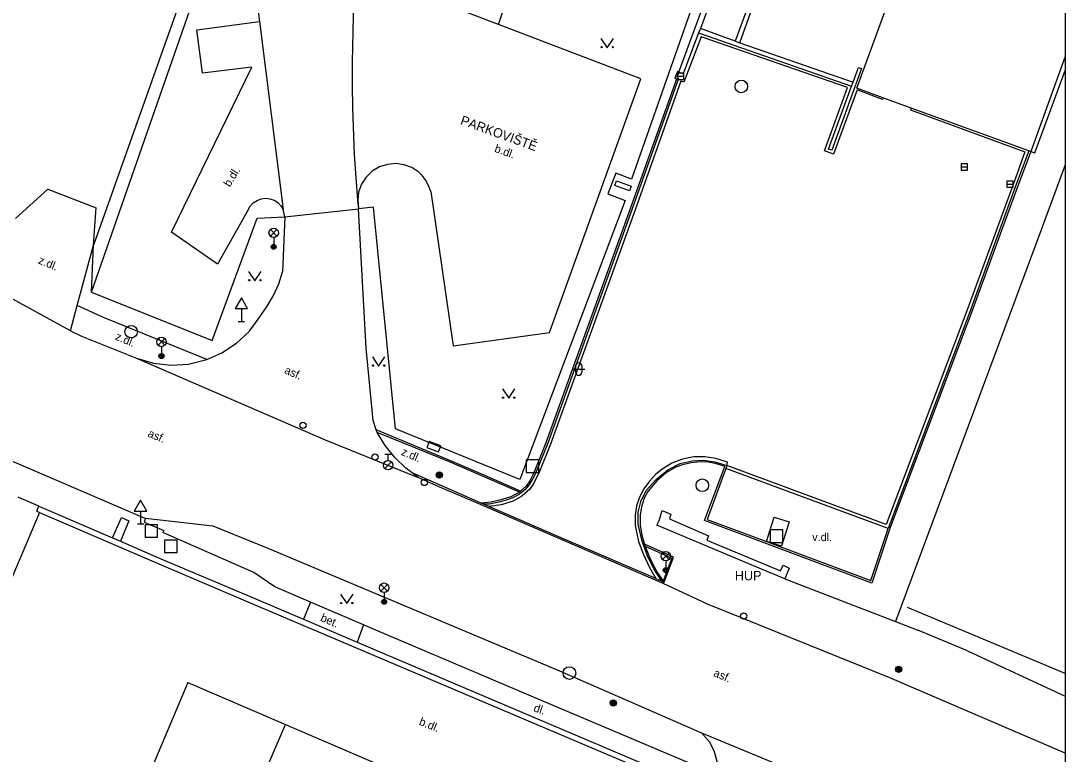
# Model space of a CAD drawing. Extents: x -596024 to -594475, y -1163820 to -1161957.
# Drawn here: x -594558.9 to -594475.5, y -1162309.5 to -1162250.9 of the extents above; entities that cross this region are included whole.
import ezdxf

# ---------------------------------------------------------------- set-up
doc = ezdxf.new("R2010")
doc.units = 0
for name, color, linetype in [('Level 10', 7, 'Continuous'), ('Level 11', 7, 'Continuous'), ('Level 14', 7, 'Continuous'), ('Level 24', 7, 'Continuous'), ('Level 25', 7, 'Continuous'), ('Level 26', 7, 'Continuous'), ('Level 27', 7, 'Continuous'), ('Level 28', 7, 'Continuous'), ('Level 33', 7, 'Continuous'), ('Level 34', 7, 'Continuous'), ('Level 36', 7, 'Continuous'), ('Level 40', 7, 'Continuous'), ('Level 41', 7, 'Continuous'), ('Level 5', 7, 'Continuous'), ('Level 7', 7, 'Continuous'), ('Level 8', 7, 'Continuous'), ('Vrstva 63', 7, 'Continuous')]:
    doc.layers.add(name, color=color, linetype=linetype)

msp = doc.modelspace()

# ---------------------------------------------------------------- linework, layer by layer
at = {"layer": 'Level 10'}
for points in [[(-594528.48, -1162197.8), (-594531.53, -1162207.45), (-594543.75, -1162242.57), (-594553.08, -1162268.85)], [(-594538.62, -1162240.19), (-594538.98, -1162241.19), (-594539.47, -1162242.7), (-594539.76, -1162243.72), (-594540.15, -1162245.26), (-594540.18, -1162246.41), (-594540.13, -1162248.13), (-594540.04, -1162249.27), (-594539.9, -1162250.41), (-594539.81, -1162250.98)], [(-594520.73, -1162251.23), (-594525.28, -1162249.49)], [(-594540.72, -1162266.03), (-594543.18, -1162270.36), (-594546.83, -1162267.81), (-594540.43, -1162254.62), (-594544.36, -1162255.11), (-594544.83, -1162251.66), (-594539.81, -1162250.98)], [(-594509.36, -1162255.56), (-594520.73, -1162251.23)], [(-594526.14, -1162264.55), (-594524.35, -1162276.86), (-594516.64, -1162275.82), (-594509.36, -1162255.56)], [(-594526.14, -1162264.55), (-594526.25, -1162264.2), (-594526.49, -1162263.71), (-594526.82, -1162263.27), (-594527.08, -1162263.02), (-594527.64, -1162262.65), (-594528.27, -1162262.42), (-594528.93, -1162262.33), (-594529.6, -1162262.39), (-594530.24, -1162262.6), (-594530.81, -1162262.94), (-594531.3, -1162263.41), (-594531.67, -1162263.97), (-594531.9, -1162264.6), (-594531.96, -1162265.22), (-594531.91, -1162265.94)], [(-594540.72, -1162266.03), (-594540.55, -1162265.72), (-594540.31, -1162265.46), (-594540.01, -1162265.27), (-594539.68, -1162265.14), (-594539.33, -1162265.1), (-594538.98, -1162265.13), (-594538.65, -1162265.25), (-594538.35, -1162265.44), (-594538.1, -1162265.69), (-594537.92, -1162265.99)], [(-594537.78, -1162266.59), (-594537.92, -1162265.99)], [(-594530.49, -1162283.58), (-594530.74, -1162282.84), (-594531.28, -1162277.05), (-594531.91, -1162265.94)], [(-594537.78, -1162266.59), (-594537.97, -1162270.97)], [(-594544.03, -1162277.97), (-594542.82, -1162277.43), (-594541.64, -1162276.66), (-594540.62, -1162275.69), (-594539.78, -1162274.56), (-594539.19, -1162273.72), (-594538.69, -1162272.86), (-594538.28, -1162271.93), (-594537.97, -1162270.97)], [(-594554.91, -1162275.67), (-594560.65, -1162272.54)], [(-594554.91, -1162275.67), (-594554.02, -1162276.1), (-594549.63, -1162277.87)], [(-594549.63, -1162277.87), (-594548.28, -1162278.26), (-594546.88, -1162278.42), (-594545.48, -1162278.33), (-594544.03, -1162277.97)], [(-594568.02, -1162282.24), (-594566.32, -1162283.19), (-594548.96, -1162290.64), (-594548.93, -1162290.64)], [(-594530.42, -1162283.78), (-594530.49, -1162283.58)], [(-594527.62, -1162287.02), (-594528.13, -1162286.64), (-594529.01, -1162285.78), (-594529.78, -1162284.83), (-594530.42, -1162283.78)], [(-594527.15, -1162287.38), (-594527.62, -1162287.02)], [(-594524.98, -1162288.34), (-594527.15, -1162287.38)], [(-594507.57, -1162295.84), (-594522.72, -1162289.3), (-594524.98, -1162288.34)], [(-594548.93, -1162290.64), (-594543.53, -1162291.24), (-594539.14, -1162293.01), (-594515.84, -1162302.8), (-594504.51, -1162307.75)], [(-594475.47, -1162309.374), (-594489.48, -1162303.37), (-594504.04, -1162297.48), (-594507.57, -1162295.84)], [(-594504.51, -1162307.75), (-594495.18, -1162311.63)]]:
    msp.add_lwpolyline(points, dxfattribs=at)
at = {"layer": 'Level 11'}
for points in [[(-594506.31, -1162255.02), (-594497.74, -1162231.74), (-594492.08, -1162216.4)], [(-594491.81, -1162216.78), (-594497.37, -1162231.89), (-594504.6, -1162251.54)], [(-594489.03, -1162217.83), (-594491.43, -1162224.29), (-594501.82, -1162252.55)], [(-594532.13, -1162246.88), (-594532.24, -1162248.72), (-594532.33, -1162250.55), (-594532.42, -1162254.23), (-594532.42, -1162256.07), (-594532.39, -1162257.91), (-594532.25, -1162261.59), (-594532.13, -1162263.43), (-594531.99, -1162265.26), (-594531.91, -1162265.94)], [(-594520.73, -1162251.23), (-594519.27, -1162246.86)], [(-594501.45, -1162252.68), (-594499.78, -1162247.95)], [(-594539.81, -1162250.98), (-594537.92, -1162265.99)], [(-594504.74, -1162251.9), (-594505.98, -1162255.17), (-594506.31, -1162255.02)], [(-594504.6, -1162251.54), (-594504.74, -1162251.9)], [(-594490.02, -1162257.08), (-594490.06, -1162257.2), (-594492.07, -1162256.45), (-594493.96, -1162261.58), (-594494.68, -1162261.31), (-594492.86, -1162256.26), (-594504.55, -1162252.2), (-594505.93, -1162255.83), (-594506.15, -1162255.76), (-594509.81, -1162266.01), (-594516.57, -1162284.73), (-594517.44, -1162286.89), (-594517.89, -1162287.83), (-594518.22, -1162288.3), (-594518.85, -1162288.88), (-594519.56, -1162289.26), (-594520.51, -1162289.56), (-594521.49, -1162289.7)], [(-594501.82, -1162252.55), (-594501.45, -1162252.68)], [(-594506.31, -1162255.02), (-594506.48, -1162255.43), (-594506.35, -1162255.53), (-594510.06, -1162265.93), (-594516.79, -1162284.63), (-594517.66, -1162286.8), (-594517.89, -1162287.33), (-594518.29, -1162287.99), (-594518.62, -1162288.36), (-594519.06, -1162288.72), (-594519.57, -1162289), (-594520.18, -1162289.23), (-594520.71, -1162289.36), (-594521.44, -1162289.5), (-594521.92, -1162289.51)], [(-594506.31, -1162255.02), (-594506.44, -1162254.97), (-594506.65, -1162255.48), (-594506.52, -1162255.58), (-594510.19, -1162265.87), (-594516.95, -1162284.61)], [(-594492.4, -1162255.82), (-594491.98, -1162254.66), (-594491.73, -1162254.75), (-594494.11, -1162261.26), (-594494.36, -1162261.17), (-594492.52, -1162256.14)], [(-594478.22, -1162261.36), (-594477.89, -1162261.48), (-594475.47, -1162254.887)], [(-594492.52, -1162256.14), (-594492.4, -1162255.82)], [(-594487.76, -1162257.9), (-594487.81, -1162258.05), (-594478.68, -1162261.39), (-594479.42, -1162263.5), (-594483.31, -1162274.08), (-594489.76, -1162291.13), (-594502.49, -1162286.43)], [(-594478.22, -1162261.36), (-594479.28, -1162264.19), (-594482.94, -1162274.22), (-594489.43, -1162291.38), (-594490.91, -1162295.81), (-594504.26, -1162290.81), (-594502.65, -1162286.5), (-594503.31, -1162286.28), (-594503.96, -1162286.16), (-594504.63, -1162286.13), (-594505.34, -1162286.2), (-594506.03, -1162286.36), (-594506.55, -1162286.56), (-594507.31, -1162286.98), (-594508.09, -1162287.65), (-594508.8, -1162288.5), (-594509.08, -1162289.04), (-594509.31, -1162289.71), (-594509.42, -1162290.38), (-594509.41, -1162291.2), (-594509.25, -1162292.08), (-594509.07, -1162292.71)], [(-594478.36, -1162261.31), (-594479.42, -1162264.14), (-594483.08, -1162274.17), (-594489.61, -1162291.44)], [(-594475.47, -1162262.421), (-594477.84, -1162268.85), (-594489.03, -1162298.88)], [(-594511.3, -1162263.71), (-594510.13, -1162264.14), (-594510.26, -1162264.51), (-594511.43, -1162264.08), (-594511.3, -1162263.71)], [(-594554.37, -1162273.65), (-594553.08, -1162268.85)], [(-594554.91, -1162275.67), (-594554.37, -1162273.65)], [(-594544.03, -1162277.97), (-594552.28, -1162274.61), (-594554.37, -1162273.65)], [(-594549.63, -1162277.87), (-594534.57, -1162284.37), (-594527.15, -1162287.38)], [(-594518.97, -1162288.46), (-594521.81, -1162287.23), (-594524.79, -1162285.94), (-594530.49, -1162283.58)], [(-594519.05, -1162288.54), (-594524.65, -1162286.14), (-594530.42, -1162283.78)], [(-594516.95, -1162284.61), (-594517.79, -1162286.75), (-594517.97, -1162287.17), (-594518.21, -1162287.65), (-594518.52, -1162288.06), (-594518.97, -1162288.46)], [(-594502.49, -1162286.43), (-594502.43, -1162286.16), (-594503.37, -1162285.86), (-594504.22, -1162285.74), (-594505.12, -1162285.74), (-594506.03, -1162285.91), (-594506.88, -1162286.25), (-594507.69, -1162286.74), (-594508.19, -1162287.15), (-594508.67, -1162287.68), (-594509.12, -1162288.28), (-594509.46, -1162288.95), (-594509.69, -1162289.64), (-594509.81, -1162290.38), (-594509.8, -1162291.18), (-594509.68, -1162291.85), (-594509.53, -1162292.48), (-594509.15, -1162293.53), (-594508.66, -1162294.57), (-594508.15, -1162295.45)], [(-594507.69, -1162295.65), (-594508.33, -1162294.66), (-594508.83, -1162293.63), (-594509.26, -1162292.47), (-594509.58, -1162291.11), (-594509.56, -1162290.14), (-594509.36, -1162289.3), (-594508.94, -1162288.43), (-594508.13, -1162287.53), (-594507.2, -1162286.77), (-594506.21, -1162286.27), (-594505.26, -1162286.06), (-594504.38, -1162286.01), (-594503.45, -1162286.13), (-594502.49, -1162286.43)], [(-594522.12, -1162289.43), (-594527.62, -1162287.02)], [(-594502.57, -1162286.65), (-594504.07, -1162290.72), (-594499.33, -1162292.5)], [(-594502.49, -1162286.43), (-594502.57, -1162286.65)], [(-594489.61, -1162291.44), (-594502.57, -1162286.65)], [(-594519.05, -1162288.54), (-594519.73, -1162288.92), (-594520.53, -1162289.17), (-594521.3, -1162289.34), (-594522.12, -1162289.43)], [(-594518.97, -1162288.46), (-594519.05, -1162288.54)], [(-594521.92, -1162289.51), (-594522.12, -1162289.43)], [(-594521.49, -1162289.7), (-594521.92, -1162289.51)], [(-594557.38, -1162290.18), (-594560.18, -1162296.77)], [(-594508.15, -1162295.45), (-594515.29, -1162292.38), (-594521.49, -1162289.7)], [(-594497.85, -1162295.47), (-594500.23, -1162294.48), (-594508.09, -1162291.19), (-594507.89, -1162290.82), (-594507.66, -1162290.01), (-594506.95, -1162290.32), (-594507.08, -1162290.68), (-594503.95, -1162292.03), (-594504.08, -1162292.38), (-594498.19, -1162294.84), (-594498, -1162294.39), (-594497.5, -1162294.61), (-594497.85, -1162295.47)], [(-594551.55, -1162292.2), (-594550.83, -1162290.57), (-594550.24, -1162290.84), (-594550.91, -1162292.47)], [(-594548.93, -1162290.64), (-594549.03, -1162290.95)], [(-594549.03, -1162290.95), (-594547.44, -1162291.62), (-594547.52, -1162291.78)], [(-594499.33, -1162292.5), (-594498.71, -1162290.56), (-594497.51, -1162290.92), (-594498.11, -1162292.86), (-594499.33, -1162292.5)], [(-594540.26, -1162294.97), (-594547.52, -1162291.78)], [(-594499.33, -1162292.5), (-594491, -1162295.61), (-594489.61, -1162291.44)], [(-594509.07, -1162292.71), (-594509.02, -1162292.87)], [(-594507.5, -1162295.74), (-594506.76, -1162293.74), (-594509.07, -1162292.71)], [(-594509.02, -1162292.87), (-594506.89, -1162293.81), (-594507.57, -1162295.65)], [(-594509.02, -1162292.87), (-594508.64, -1162293.83), (-594508.09, -1162294.9), (-594507.57, -1162295.65)], [(-594538.6, -1162296.12), (-594540.26, -1162294.97)], [(-594508.15, -1162295.45), (-594507.69, -1162295.65)], [(-594497.85, -1162295.47), (-594489.03, -1162298.88), (-594487.24, -1162299.57)], [(-594535.75, -1162297.34), (-594538.6, -1162296.12)], [(-594507.69, -1162295.65), (-594507.5, -1162295.74)], [(-594507.57, -1162295.65), (-594507.5, -1162295.74)], [(-594507.57, -1162295.84), (-594507.5, -1162295.74)], [(-594535.75, -1162297.34), (-594536.3, -1162298.7)], [(-594531.5, -1162299.13), (-594535.75, -1162297.34)], [(-594531.5, -1162299.13), (-594532.02, -1162300.52)], [(-594530.51, -1162299.56), (-594531.5, -1162299.13)], [(-594517.23, -1162305.21), (-594530.51, -1162299.56)], [(-594503.21, -1162311.14), (-594517.23, -1162305.21)], [(-594504.51, -1162307.75), (-594503.9, -1162308.46), (-594503.53, -1162309.18), (-594503.23, -1162310.2), (-594503.21, -1162311.14)]]:
    msp.add_lwpolyline(points, dxfattribs=at)
at = {"layer": 'Level 14'}
for p, q in [((-594475.47, -1162303.022), (-594488.06, -1162297.76)), ((-594483.27, -1162301.21), (-594475.47, -1162304.823))]:
    msp.add_line(p, q, dxfattribs=at)
at = {"layer": 'Level 24'}
for points in [[(-594504.74, -1162251.9), (-594492.52, -1162256.14)], [(-594501.82, -1162252.55), (-594504.6, -1162251.54)], [(-594501.45, -1162252.68), (-594492.4, -1162255.82)]]:
    msp.add_lwpolyline(points, dxfattribs=at)
msp.add_lwpolyline([(-594526.446, -1162284.98), (-594525.508, -1162285.328), (-594525.334, -1162284.86), (-594526.272, -1162284.512)], close=True, dxfattribs=at)
at = {"layer": 'Level 25'}
for centre, radius in [((-594525.45, -1162287.18), 0.25), ((-594525.45, -1162287.18), 0.2), ((-594525.45, -1162287.18), 0.15), ((-594525.45, -1162287.18), 0.1), ((-594525.45, -1162287.18), 0.05), ((-594488.77, -1162302.7), 0.25), ((-594488.77, -1162302.7), 0.2), ((-594488.77, -1162302.7), 0.15), ((-594488.77, -1162302.7), 0.1), ((-594488.77, -1162302.7), 0.05), ((-594511.56, -1162305.37), 0.25), ((-594511.56, -1162305.37), 0.2), ((-594511.56, -1162305.37), 0.15), ((-594511.56, -1162305.37), 0.1), ((-594511.56, -1162305.37), 0.05)]:
    msp.add_circle(centre, radius, dxfattribs=at)
at = {"layer": 'Level 26'}
for points in [[(-594518.51, -1162286.97), (-594517.51, -1162286.97), (-594517.51, -1162285.97), (-594518.51, -1162285.97)], [(-594548.95, -1162292.15), (-594547.95, -1162292.15), (-594547.95, -1162291.15), (-594548.95, -1162291.15)], [(-594499.02, -1162292.57), (-594498.02, -1162292.57), (-594498.02, -1162291.57), (-594499.02, -1162291.57)], [(-594547.39, -1162293.37), (-594546.39, -1162293.37), (-594546.39, -1162292.37), (-594547.39, -1162292.37)]]:
    msp.add_lwpolyline(points, close=True, dxfattribs=at)
at = {"layer": 'Level 27'}
for p, q in [((-594506.42, -1162255.36), (-594505.92, -1162255.36)), ((-594483.76, -1162262.6), (-594483.26, -1162262.6)), ((-594480.13, -1162263.97), (-594479.63, -1162263.97))]:
    msp.add_line(p, q, dxfattribs=at)
for points in [[(-594506.42, -1162255.61), (-594505.92, -1162255.61), (-594505.92, -1162255.11), (-594506.42, -1162255.11)], [(-594483.76, -1162262.85), (-594483.26, -1162262.85), (-594483.26, -1162262.35), (-594483.76, -1162262.35)], [(-594480.13, -1162264.22), (-594479.63, -1162264.22), (-594479.63, -1162263.72), (-594480.13, -1162263.72)]]:
    msp.add_lwpolyline(points, close=True, dxfattribs=at)
for centre in [(-594501.33, -1162256.17), (-594550.06, -1162275.74), (-594504.45, -1162288), (-594515.06, -1162302.99)]:
    msp.add_circle(centre, 0.5, dxfattribs=at)
at = {"layer": 'Level 28'}
for p, q in [((-594529.798, -1162286.672), (-594529.268, -1162286.142)), ((-594529.79, -1162285.525), (-594529.29, -1162285.525)), ((-594529.54, -1162286.025), (-594529.54, -1162285.525))]:
    msp.add_line(p, q, dxfattribs=at)
for centre, radius in [((-594536.34, -1162283.21), 0.25), ((-594530.59, -1162285.74), 0.25), ((-594529.54, -1162286.4), 0.375), ((-594526.64, -1162287.78), 0.25), ((-594501.15, -1162298.43), 0.25)]:
    msp.add_circle(centre, radius, dxfattribs=at)
at = {"layer": 'Level 33'}
for p, q in [((-594538.945, -1162268.11), (-594538.415, -1162267.58)), ((-594538.945, -1162267.58), (-594538.415, -1162268.11)), ((-594538.68, -1162268.22), (-594538.68, -1162268.97)), ((-594547.915, -1162276.83), (-594547.385, -1162276.3)), ((-594547.915, -1162276.3), (-594547.385, -1162276.83)), ((-594547.65, -1162276.94), (-594547.65, -1162277.69)), ((-594507.635, -1162293.92), (-594507.105, -1162293.39)), ((-594507.635, -1162293.39), (-594507.105, -1162293.92)), ((-594507.37, -1162294.03), (-594507.37, -1162294.78)), ((-594530.125, -1162296.44), (-594529.595, -1162295.91)), ((-594530.125, -1162295.91), (-594529.595, -1162296.44)), ((-594529.86, -1162296.55), (-594529.86, -1162297.3))]:
    msp.add_line(p, q, dxfattribs=at)
for centre, radius in [((-594538.68, -1162267.845), 0.375), ((-594538.68, -1162268.97), 0.2), ((-594538.68, -1162268.97), 0.145), ((-594538.68, -1162268.97), 0.0876), ((-594547.65, -1162276.565), 0.375), ((-594547.65, -1162277.69), 0.2), ((-594547.65, -1162277.69), 0.145), ((-594547.65, -1162277.69), 0.0876), ((-594507.37, -1162293.655), 0.375), ((-594507.37, -1162294.78), 0.2), ((-594507.37, -1162294.78), 0.145), ((-594507.37, -1162294.78), 0.0876), ((-594529.86, -1162296.175), 0.375), ((-594529.86, -1162297.3), 0.2), ((-594529.86, -1162297.3), 0.145), ((-594529.86, -1162297.3), 0.0876)]:
    msp.add_circle(centre, radius, dxfattribs=at)
at = {"layer": 'Level 34'}
for p, q in [((-594541.26, -1162273.902), (-594541.26, -1162274.92)), ((-594541.51, -1162274.92), (-594541.01, -1162274.92)), ((-594549.31, -1162290.062), (-594549.31, -1162291.08)), ((-594549.56, -1162291.08), (-594549.06, -1162291.08))]:
    msp.add_line(p, q, dxfattribs=at)
for points in [[(-594541.76, -1162273.902), (-594540.76, -1162273.902), (-594541.26, -1162273.036)], [(-594549.81, -1162290.062), (-594548.81, -1162290.062), (-594549.31, -1162289.196)]]:
    msp.add_lwpolyline(points, close=True, dxfattribs=at)
at = {"layer": 'Level 36'}
for p, q in [((-594514.816, -1162278.726), (-594513.816, -1162278.726)), ((-594514.566, -1162278.476), (-594514.566, -1162278.976)), ((-594514.066, -1162278.476), (-594514.066, -1162278.976))]:
    msp.add_line(p, q, dxfattribs=at)
for points in [[(-594512.54, -1162252.34), (-594512.04, -1162253.09), (-594511.54, -1162252.34)], [(-594540.68, -1162270.94), (-594540.18, -1162271.69), (-594539.68, -1162270.94)], [(-594530.8, -1162277.75), (-594530.3, -1162278.5), (-594529.8, -1162277.75)], [(-594520.41, -1162280.31), (-594519.91, -1162281.06), (-594519.41, -1162280.31)], [(-594533.34, -1162296.7), (-594532.84, -1162297.45), (-594532.34, -1162296.7)]]:
    msp.add_lwpolyline(points, dxfattribs=at)
for centre in [(-594512.49, -1162253.04), (-594511.591, -1162253.04), (-594540.63, -1162271.64), (-594539.731, -1162271.64), (-594530.75, -1162278.45), (-594529.851, -1162278.45), (-594520.36, -1162281.01), (-594519.461, -1162281.01), (-594533.29, -1162297.4), (-594532.391, -1162297.4)]:
    msp.add_circle(centre, 0.05, dxfattribs=at)
for centre, start, end in [((-594514.316, -1162278.476), 0, 180), ((-594514.316, -1162278.976), 180, 0)]:
    msp.add_arc(centre, 0.25, start, end, dxfattribs=at)
at = {"layer": 'Level 5'}
msp.add_line((-594475.47, -1162253.79), (-594478.22, -1162261.36), dxfattribs=at)
for points in [[(-594492.11, -1162256.32), (-594487.32, -1162243.21)], [(-594490.02, -1162257.08), (-594492.11, -1162256.32)], [(-594487.76, -1162257.9), (-594490.02, -1162257.08)], [(-594478.36, -1162261.31), (-594487.76, -1162257.9)], [(-594478.22, -1162261.36), (-594478.36, -1162261.31)], [(-594545.53, -1162303.75), (-594555.23, -1162326.7)], [(-594545.53, -1162303.75), (-594537.74, -1162307.1), (-594508.18, -1162319.79)], [(-594541.76, -1162316.42), (-594537.74, -1162307.1)]]:
    msp.add_lwpolyline(points, dxfattribs=at)
at = {"layer": 'Level 7'}
for points in [[(-594553.22, -1162272.58), (-594547.15, -1162255.2), (-594541.62, -1162239.3), (-594537.34, -1162227.09), (-594532.8, -1162214), (-594528.53, -1162201.79), (-594524.76, -1162190.99), (-594520.91, -1162179.95), (-594517.77, -1162170.97)], [(-594485.59, -1162192.97), (-594492.91, -1162214.34), (-594501.91, -1162240.21), (-594510.1, -1162263.56)], [(-594510.1, -1162263.56), (-594511.35, -1162263.08), (-594511.99, -1162264.75), (-594510.6, -1162265.28), (-594519.01, -1162287.54)], [(-594556.73, -1162264.38), (-594559.3, -1162266.72)], [(-594553.08, -1162268.85), (-594552.86, -1162265.87)], [(-594519.01, -1162287.54), (-594528.94, -1162283.5), (-594530.7, -1162265.8), (-594531.91, -1162265.94)], [(-594543.59, -1162276.46), (-594540.01, -1162266.69), (-594537.78, -1162266.59)], [(-594553.22, -1162272.58), (-594553.08, -1162268.85)], [(-594553.22, -1162272.58), (-594543.59, -1162276.46)], [(-594557.6, -1162290.08), (-594557.43, -1162289.67)], [(-594557.6, -1162290.08), (-594557.38, -1162290.18)], [(-594557.43, -1162289.67), (-594551.55, -1162292.2)], [(-594557.38, -1162290.18), (-594548.05, -1162294.19)], [(-594551.55, -1162292.2), (-594550.91, -1162292.47)], [(-594550.91, -1162292.47), (-594547.87, -1162293.78)], [(-594547.87, -1162293.78), (-594540.75, -1162296.81), (-594536.3, -1162298.7)], [(-594548.05, -1162294.19), (-594540.93, -1162297.22)], [(-594540.93, -1162297.22), (-594503.92, -1162312.92)], [(-594536.3, -1162298.7), (-594532.02, -1162300.52)], [(-594532.02, -1162300.52), (-594503.76, -1162312.52)]]:
    msp.add_lwpolyline(points, dxfattribs=at)
at = {"layer": 'Level 8'}
for points in [[(-594556.73, -1162264.38), (-594552.86, -1162265.87)], [(-594537.78, -1162266.59), (-594531.91, -1162265.94)], [(-594557.43, -1162289.67), (-594559.09, -1162288.96)], [(-594483.27, -1162301.21), (-594487.24, -1162299.57)]]:
    msp.add_lwpolyline(points, dxfattribs=at)
at = {"layer": 'Vrstva 63'}
msp.add_lwpolyline([(-594475.47, -1163820.23), (-596024.42, -1163820.23), (-596024.42, -1161956.88), (-594475.47, -1161956.88)], close=True, dxfattribs=at)

# ---------------------------------------------------------------- texts
at = {"layer": 'Level 40'}
for s, rotation, p in [('b.dl.', 340.23, (-594521.1, -1162261.38)), ('b.dl.', 57.86, (-594542.19, -1162264.24)), ('z.dl.', 337.7, (-594557.54, -1162270.28)), ('z.dl.', 337.1, (-594551.39, -1162276.36)), ('asf.', 337.1, (-594537.88, -1162279.05)), ('asf.', 337.1, (-594548.79, -1162284.09)), ('z.dl.', 337.1, (-594528.55, -1162285.56)), ('bet.', 336.95, (-594535, -1162298.81)), ('asf.', 337.1, (-594503.61, -1162303.21)), ('dl.', 341.56, (-594517.97, -1162306.03)), ('b.dl.', 338.13, (-594527.12, -1162307.1))]:
    msp.add_text(s, height=0.65, rotation=rotation, dxfattribs=at).set_placement(p)
msp.add_text('v.dl.', height=0.65, dxfattribs=at).set_placement((-594495.67, -1162292.46))
at = {"layer": 'Level 41'}
msp.add_text(' PARKOVIŠTĚ', height=0.75, rotation=340.23, dxfattribs=at).set_placement((-594524.09, -1162259.08))
msp.add_text('HUP', height=0.75, dxfattribs=at).set_placement((-594501.84, -1162295.59))

doc.saveas('drawing.dxf')
